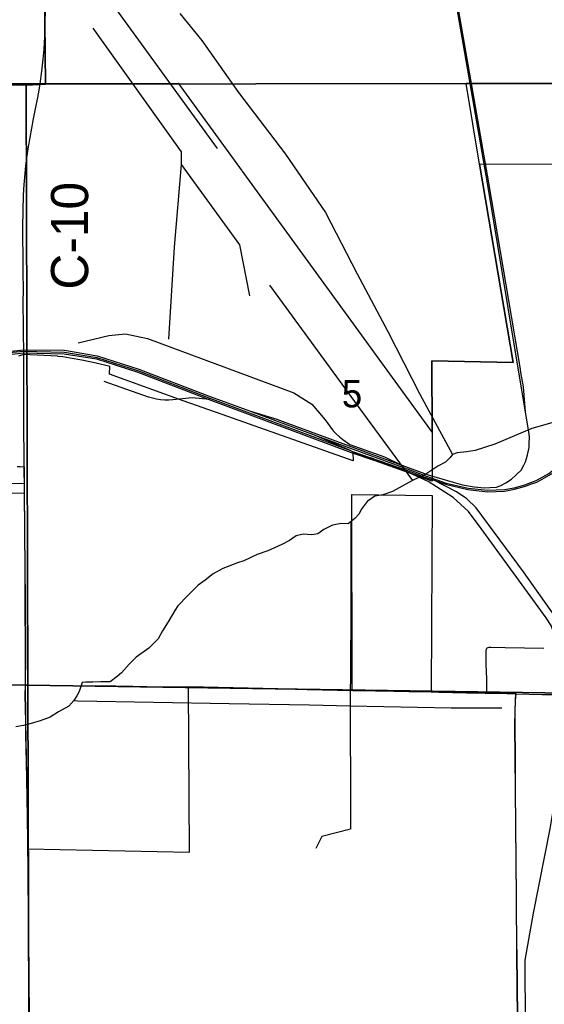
# Model space of a CAD drawing. Extents: x 0 to 40.2, y 0 to 22.
# Drawn here: x 3.735 to 4.538, y 14.848 to 16.354 of the extents above; entities that cross this region are included whole.
import ezdxf

# ---------------------------------------------------------------- set-up
doc = ezdxf.new("R2010")
doc.units = 0
for name, color, linetype in [('GM_X_City_Street', 7, 'Continuous'), ('GM_X_Corporation', 7, 'Continuous'), ('GM_X_Major_Lake_Text', 7, 'Continuous'), ('GM_X_Major_River', 7, 'Continuous'), ('GM_X_Minor_Lake', 7, 'Continuous'), ('GM_X_Rail_Line', 7, 'Continuous'), ('GM_X_Rail_Line_Text', 7, 'Continuous'), ('GM_X_Unincorporated_Location', 7, 'Continuous')]:
    doc.layers.add(name, color=color, linetype=linetype)

msp = doc.modelspace()

# ---------------------------------------------------------------- linework, layer by layer
at = {"layer": 'GM_X_Corporation'}
for points in [[(2.9622, 17.2582), (3.7642, 17.2609), (3.7748, 16.2549), (3.7456, 16.2537), (2.955, 16.2539), (2.9579, 16.7917)], [(4.773, 17.2675), (4.7705, 16.2552), (4.7398, 16.2563), (3.7748, 16.2549), (3.7642, 17.2609)], [(2.955, 16.2539), (3.7456, 16.2537), (3.7481, 15.3357), (2.9569, 15.3522), (2.9567, 15.7585)], [(3.7748, 16.2549), (4.7398, 16.2563), (4.745, 15.3208), (3.7481, 15.3357), (3.7456, 16.2537)], [(2.9569, 15.3522), (3.7481, 15.3357), (3.751, 14.324), (2.9499, 14.3312), (2.9519, 14.728)], [(3.7481, 15.3357), (4.745, 15.3208), (4.749, 14.3145), (3.751, 14.324)]]:
    msp.add_lwpolyline(points, close=True, dxfattribs=at)
for points in [[(2.952, 16.2558), (3.7668, 16.256), (3.978, 16.2564), (4.3662, 15.7222), (4.3657, 15.832), (4.4899, 15.8293), (4.4389, 16.1327), (4.4182, 16.2558), (4.7417, 16.2555), (5.5568, 16.2525), (5.5984, 16.253), (5.6048, 16.2528), (5.7527, 16.2521)], [(4.641, 16.1323), (4.4389, 16.1327), (4.4899, 15.8293), (4.3657, 15.832), (4.3662, 15.7222), (4.3661, 15.648), (4.2451, 15.6912), (4.2454, 15.6788), (4.0452, 15.7495), (3.9856, 15.7704), (3.8729, 15.8116), (3.8731, 15.8234), (3.8524, 15.8284), (3.8303, 15.8329), (3.8128, 15.836), (3.8015, 15.8377), (3.7945, 15.8386), (3.7931, 15.839), (3.7415, 15.8413), (3.7335, 15.8389)], [(3.7317, 15.6703), (3.7362, 15.6702), (3.7423, 15.6699), (3.7423, 15.6437), (3.541, 15.649)], [(3.5433, 15.6343), (3.7424, 15.6292), (3.7429, 15.5757), (3.7435, 15.5098), (3.7437, 15.4706), (3.7442, 15.3829), (3.7441, 15.3362), (3.7438, 15.3204), (3.7442, 15.3011), (3.7445, 15.2804), (3.7477, 15.0853), (3.9951, 15.0801), (3.9937, 15.3336), (4.2441, 15.3281), (4.2434, 15.6275), (4.3661, 15.626), (4.3645, 15.3261), (4.3761, 15.3256), (4.4184, 15.3246), (4.447, 15.3242), (4.4496, 15.3242), (4.4664, 15.324), (4.494, 15.3231), (4.4934, 15.3124), (4.4928, 15.2955), (4.4926, 15.2761), (4.4926, 15.2674), (4.493, 15.232), (4.4933, 15.1711), (4.4938, 15.1263), (4.4944, 15.0635), (4.4949, 15.015), (4.4949, 14.992), (4.4953, 14.9454), (4.4956, 14.918), (4.496, 14.8832), (4.4967, 14.8215)]]:
    msp.add_lwpolyline(points, dxfattribs=at)
at = {"layer": 'GM_X_Major_Lake_Text'}
for points in [[(3.767, 16.2555), (3.7693, 16.2747), (3.7715, 16.2932), (3.7729, 16.3087), (3.7739, 16.3273), (3.7746, 16.3484), (3.7748, 16.3688), (3.7748, 16.3921)], [(3.7417, 15.8408), (3.7416, 15.852), (3.7413, 15.8675), (3.7412, 15.8899), (3.741, 15.9154), (3.7412, 15.9464), (3.7409, 15.962), (3.7406, 15.9787), (3.7404, 16.0341), (3.7406, 16.0633), (3.7412, 16.0832), (3.7418, 16.095), (3.745, 16.1303), (3.7464, 16.1421), (3.7491, 16.1593), (3.7568, 16.2022), (3.7582, 16.2095), (3.7602, 16.2199), (3.7627, 16.232), (3.7648, 16.2429), (3.767, 16.2555)], [(3.7425, 15.6694), (3.7424, 15.6796), (3.7418, 15.735), (3.7419, 15.7661), (3.7417, 15.7891), (3.7418, 15.8158), (3.7417, 15.8408)], [(3.7426, 15.6432), (3.7425, 15.6628), (3.7425, 15.6694)], [(3.7426, 15.6286), (3.7426, 15.6317), (3.7426, 15.6432)], [(3.7443, 15.3356), (3.7444, 15.3824), (3.7439, 15.4701), (3.7437, 15.5093), (3.7431, 15.5751), (3.7426, 15.6286)], [(3.7447, 15.2799), (3.7444, 15.3005), (3.744, 15.3198), (3.7443, 15.3356)], [(3.7479, 15.0847), (3.7477, 15.0973), (3.7472, 15.1346), (3.7465, 15.1918), (3.7459, 15.2173), (3.745, 15.2608), (3.7447, 15.2799)], [(3.7538, 14.5772), (3.7535, 14.6069), (3.7529, 14.6423), (3.7523, 14.6784), (3.7518, 14.7244), (3.7512, 14.7716), (3.7508, 14.8033), (3.7502, 14.8767), (3.7501, 14.8978), (3.7495, 14.9426), (3.7491, 14.9997), (3.7487, 15.0289), (3.7482, 15.0619), (3.7479, 15.0847)]]:
    msp.add_lwpolyline(points, dxfattribs=at)
at = {"layer": 'GM_X_Major_River'}
for p, q in [((4.5089, 15.754), (4.4984, 15.8177)), ((4.0868, 15.7555), (4.1804, 15.7209)), ((4.2413, 15.6946), (4.1804, 15.7209))]:
    msp.add_line(p, q, dxfattribs=at)
for points in [[(4.4984, 15.8177), (4.4509, 16.1036), (4.3365, 16.7608), (4.2596, 17.2111), (4.2446, 17.2471), (4.2325, 17.2675), (4.2194, 17.2862), (4.173, 17.3292), (4.0811, 17.4144)], [(4.5011, 15.819), (4.4528, 16.1039), (4.3383, 16.7612), (4.2614, 17.2116), (4.2462, 17.2479), (4.2341, 17.2685), (4.2208, 17.2874), (4.1742, 17.3305), (4.0824, 17.4158)], [(4.038, 16.1564), (3.6914, 16.634), (3.2424, 17.2551), (3.2285, 17.2744), (3.2047, 17.2941), (3.2047, 17.2941)], [(3.825, 15.8593), (3.8717, 15.8705), (3.8974, 15.8731), (3.9309, 15.8659), (4.1545, 15.783), (4.1821, 15.7653), (4.2025, 15.7416), (4.211, 15.7302), (4.2151, 15.725), (4.2196, 15.7201), (4.2244, 15.7155), (4.2296, 15.7113), (4.2404, 15.704), (4.2933, 15.6849), (4.3194, 15.6724)], [(3.3179, 15.804), (3.5059, 15.8224), (3.6497, 15.8372), (3.7409, 15.8466), (3.8039, 15.8452), (3.8533, 15.8371), (3.9171, 15.8167), (4.0206, 15.7769), (4.2413, 15.6946)], [(3.6385, 15.8323), (3.7411, 15.8442), (3.8037, 15.8423), (3.8527, 15.8349), (3.9164, 15.8145), (4.0198, 15.7747), (4.2425, 15.6914), (4.2786, 15.6792), (4.2945, 15.6737), (4.3278, 15.6622)], [(3.6388, 15.838), (3.7417, 15.8485), (3.8038, 15.848), (3.8539, 15.8394), (3.9179, 15.8189), (4.0214, 15.7791), (4.0868, 15.7555)], [(4.5089, 15.754), (4.5057, 15.7919), (4.502, 15.814), (4.5011, 15.819)], [(4.0256, 15.7727), (3.9993, 15.7752), (3.9697, 15.7721), (3.9635, 15.7717), (3.9572, 15.7718), (3.9509, 15.7723), (3.9448, 15.7732), (3.9386, 15.7746), (3.9327, 15.7765), (3.8645, 15.8001)], [(4.0868, 15.7555), (4.1285, 15.7424), (4.1448, 15.7366), (4.299, 15.6799), (4.3602, 15.6575), (4.3985, 15.6461), (4.4126, 15.6422), (4.4304, 15.639), (4.4458, 15.6374), (4.4544, 15.6379), (4.4648, 15.6387), (4.4713, 15.6411), (4.4787, 15.6452), (4.4874, 15.6508), (4.5024, 15.6646), (4.5064, 15.6723), (4.5088, 15.6773), (4.5107, 15.6826), (4.5121, 15.688), (4.5136, 15.6946), (4.5144, 15.6993), (4.5147, 15.7039), (4.5149, 15.7164), (4.5148, 15.7182), (4.5146, 15.7199), (4.5089, 15.754)], [(4.1804, 15.7209), (4.2441, 15.6973), (4.3298, 15.666), (4.3576, 15.6554), (4.3877, 15.6449), (4.4214, 15.6372), (4.4513, 15.634), (4.4767, 15.6351), (4.4919, 15.6378), (4.5082, 15.6421), (4.5174, 15.6459), (4.5251, 15.6486), (4.5445, 15.6593), (4.5605, 15.6717), (4.5912, 15.7043)], [(4.2413, 15.6946), (4.2445, 15.6934), (4.3268, 15.6647), (4.3551, 15.6541), (4.3688, 15.6493)], [(4.3688, 15.6493), (4.3864, 15.643), (4.4209, 15.635), (4.4512, 15.6317), (4.477, 15.6327), (4.4924, 15.6355), (4.5089, 15.6399), (4.5182, 15.6437), (4.5261, 15.6464), (4.5488, 15.659), (4.5629, 15.6683), (4.5931, 15.703)], [(4.5484, 15.4269), (4.5407, 15.4386), (4.4412, 15.5756), (4.422, 15.6015), (4.3982, 15.6228), (4.3599, 15.6474), (4.3293, 15.6616), (4.2723, 15.6837)], [(5.535, 14.1), (5.3096, 14.4085), (4.8372, 15.0553), (4.7454, 15.1806), (4.5642, 15.4272), (4.5058, 15.5092), (4.4338, 15.6071), (4.4191, 15.6206), (4.4034, 15.6315), (4.3688, 15.6493)], [(4.5972, 14.4353), (4.551, 14.5199), (4.5329, 14.5716), (4.5206, 14.6267), (4.5091, 14.7122), (4.5091, 14.8158), (4.5083, 14.9152), (4.5214, 14.9868), (4.5469, 15.1158), (4.5617, 15.2046), (4.5708, 15.2778), (4.572, 15.3374), (4.5642, 15.3826), (4.5484, 15.4269)]]:
    msp.add_lwpolyline(points, dxfattribs=at)
at = {"layer": 'GM_X_Minor_Lake'}
for points in [[(3.9803, 16.3631), (4.0138, 16.3217), (4.0701, 16.242), (4.1418, 16.1478), (4.203, 16.0589), (4.2516, 15.965), (4.2984, 15.8767), (4.3474, 15.7809), (4.3976, 15.6884), (4.3934, 15.6835), (4.3865, 15.6768), (4.3751, 15.6705), (4.3568, 15.6586), (4.3363, 15.6489), (4.3058, 15.6319), (4.2906, 15.6267), (4.2785, 15.6246), (4.2667, 15.6168), (4.2575, 15.6044), (4.2544, 15.5976), (4.2482, 15.5905), (4.2379, 15.5826), (4.227, 15.5828), (4.2137, 15.5807), (4.2004, 15.5736), (4.1916, 15.5673), (4.1825, 15.5655), (4.169, 15.5668), (4.1583, 15.5643), (4.1481, 15.5572), (4.1363, 15.5509), (4.1252, 15.5457), (4.115, 15.5413), (4.0987, 15.5354), (4.0781, 15.5258), (4.0686, 15.5229), (4.0459, 15.5141), (4.0314, 15.5059), (4.0192, 15.4966), (4.0085, 15.4887), (3.9928, 15.473), (3.9771, 15.4573), (3.9725, 15.4501), (3.9624, 15.4328), (3.954, 15.4188), (3.947, 15.4064), (3.9328, 15.3922), (3.9134, 15.3788), (3.9027, 15.3679), (3.8912, 15.3547), (3.8847, 15.3488), (3.874, 15.3409), (3.8598, 15.3408), (3.8471, 15.3405), (3.8366, 15.3403), (3.8309, 15.3399), (3.8266, 15.326), (3.8231, 15.3195), (3.8184, 15.3124), (3.8108, 15.3038), (3.7948, 15.2949)], [(3.8474, 16.3404), (3.9824, 16.1513), (3.9822, 16.1319), (3.9715, 16.0057), (3.9628, 15.865)], [(3.9822, 16.1319), (4.0716, 16.009), (4.0868, 15.9314)], [(4.1177, 15.9473), (4.2104, 15.8205), (4.2654, 15.7451), (4.3363, 15.6489)], [(5.5489, 15.8408), (5.4998, 15.8245), (5.4804, 15.818), (5.4675, 15.8132), (5.4603, 15.8122), (5.4062, 15.8116), (5.2968, 15.8114), (5.245, 15.813), (5.1266, 15.8146), (4.9988, 15.8147), (4.8887, 15.8158), (4.8002, 15.8172), (4.7741, 15.8161), (4.6767, 15.7828), (4.6101, 15.7576), (4.5602, 15.7399), (4.5188, 15.7284), (4.4621, 15.7046), (4.432, 15.6949), (4.4188, 15.6924), (4.4043, 15.6911), (4.3976, 15.6884)], [(4.2417, 15.5849), (4.2417, 15.438), (4.2407, 15.3044), (4.2413, 15.1496), (4.2412, 15.1154), (4.1973, 15.1042), (4.1883, 15.0857)], [(3.8184, 15.3124), (3.8243, 15.3119), (4.056, 15.3079), (4.1788, 15.3056), (4.2407, 15.3044), (4.3952, 15.301)], [(4.3952, 15.301), (4.4727, 15.3009)], [(3.7948, 15.2949), (3.7819, 15.287), (3.767, 15.2812), (3.753, 15.2772), (3.7413, 15.2739), (3.7295, 15.2718)]]:
    msp.add_lwpolyline(points, dxfattribs=at)
at = {"layer": 'GM_X_Rail_Line'}
msp.add_line((3.8404, 15.3349), (3.8414, 15.3349), dxfattribs=at)
for points in [[(3.5845, 15.3384), (3.5866, 15.3384), (3.5978, 15.3384), (3.6351, 15.3381), (3.6612, 15.3377), (3.6904, 15.3372), (3.7072, 15.3369), (3.7308, 15.3364), (3.7443, 15.3356)], [(3.7443, 15.3356), (3.8118, 15.335), (3.8404, 15.3349)], [(3.8414, 15.3349), (3.8823, 15.3346), (3.9084, 15.3343), (3.9513, 15.3334), (3.9625, 15.3334), (3.9836, 15.3332), (3.9939, 15.333), (3.9949, 15.333)], [(3.9949, 15.333), (4.0651, 15.3311), (4.0974, 15.3307), (4.139, 15.33), (4.1751, 15.3292), (4.245, 15.3278), (4.246, 15.3278)], [(4.246, 15.3278), (4.2628, 15.3275), (4.2796, 15.3272), (4.3076, 15.3266), (4.3306, 15.3262), (4.3493, 15.3259), (4.3647, 15.3255)], [(4.3647, 15.3255), (4.3763, 15.325), (4.4186, 15.324), (4.4472, 15.3236), (4.4498, 15.3236)], [(4.4498, 15.3236), (4.4666, 15.3235), (4.4943, 15.3225)], [(4.4969, 14.8209), (4.4962, 14.8827), (4.4958, 14.9175), (4.4955, 14.9448), (4.4951, 14.9914), (4.4952, 15.0145), (4.4946, 15.063), (4.4941, 15.1257), (4.4936, 15.1705), (4.4932, 15.2314), (4.4928, 15.2669), (4.4928, 15.2756), (4.493, 15.295), (4.4936, 15.3119), (4.4943, 15.3225)], [(4.4943, 15.3225), (4.5346, 15.3216), (4.5563, 15.3213), (4.5687, 15.321), (4.5855, 15.3204), (4.5922, 15.3201)]]:
    msp.add_lwpolyline(points, dxfattribs=at)
at = {"layer": 'GM_X_Unincorporated_Location'}
for points in [[(4.4498, 15.3236), (4.4498, 15.3311), (4.4497, 15.3448), (4.4488, 15.3678), (4.4486, 15.3866), (4.4487, 15.3881), (4.4488, 15.3894), (4.4491, 15.3905), (4.4494, 15.3913), (4.4498, 15.3921)], [(4.4498, 15.3921), (4.4505, 15.3927), (4.4511, 15.3931), (4.4519, 15.3934), (4.4532, 15.3937), (4.4546, 15.3939), (4.456, 15.3939), (4.4779, 15.3936), (4.5368, 15.3924)]]:
    msp.add_lwpolyline(points, dxfattribs=at)

# ---------------------------------------------------------------- texts
at = {"layer": 'GM_X_City_Street'}
msp.add_text('5', height=0.0419, rotation=0, dxfattribs=at).set_placement((4.2281, 15.7606))
at = {"layer": 'GM_X_Rail_Line_Text'}
msp.add_text('C-10', height=0.05682, rotation=90, dxfattribs=at).set_placement((3.8402, 15.9408))

doc.saveas('drawing.dxf')
